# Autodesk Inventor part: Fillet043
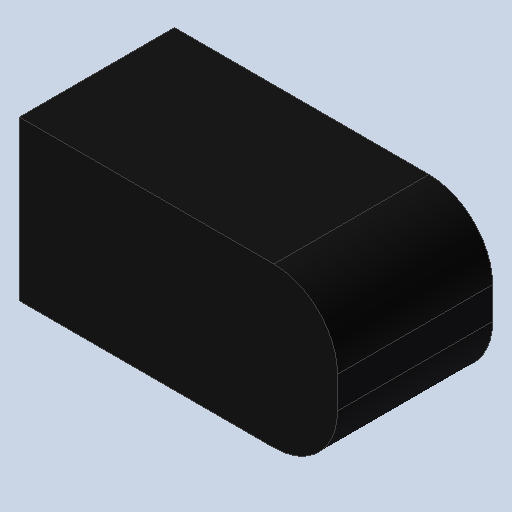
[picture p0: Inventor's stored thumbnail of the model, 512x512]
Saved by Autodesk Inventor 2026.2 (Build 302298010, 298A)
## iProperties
Created: 2026-10
Part Number: Fillet043
Material: Générique
Document SubType Name: Modeling
Designer: mel
Density: 1 g/cm^3
Appearance: Par défaut
Author: mel
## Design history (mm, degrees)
feature "Base1"
node "Solide1"
